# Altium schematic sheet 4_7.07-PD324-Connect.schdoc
size 848 x 601 mm; Symbol: Drawing-Symbol_A1; Device: Drawing-Symbol_A1; Company: 嘉立创EDA; Version: V1.0; Page Size: A1; @Project Name: PD324; @Page Count: 4; @Update Date: 2025-05-07; @Create Date: 2025-05-06; @Schematic Name: Schematic1; @Page No: 4; @Page Name: 7.07-PD324-Connect; @Create Time: 08:53:41; @Update Time: 09:37:43; Width: 3304; Height: 2338; Region Start: 1; X Region Count: 6; Y Region Count: 4; Blade Width: 10; Title Block Position: 3; @Board Name: Board1
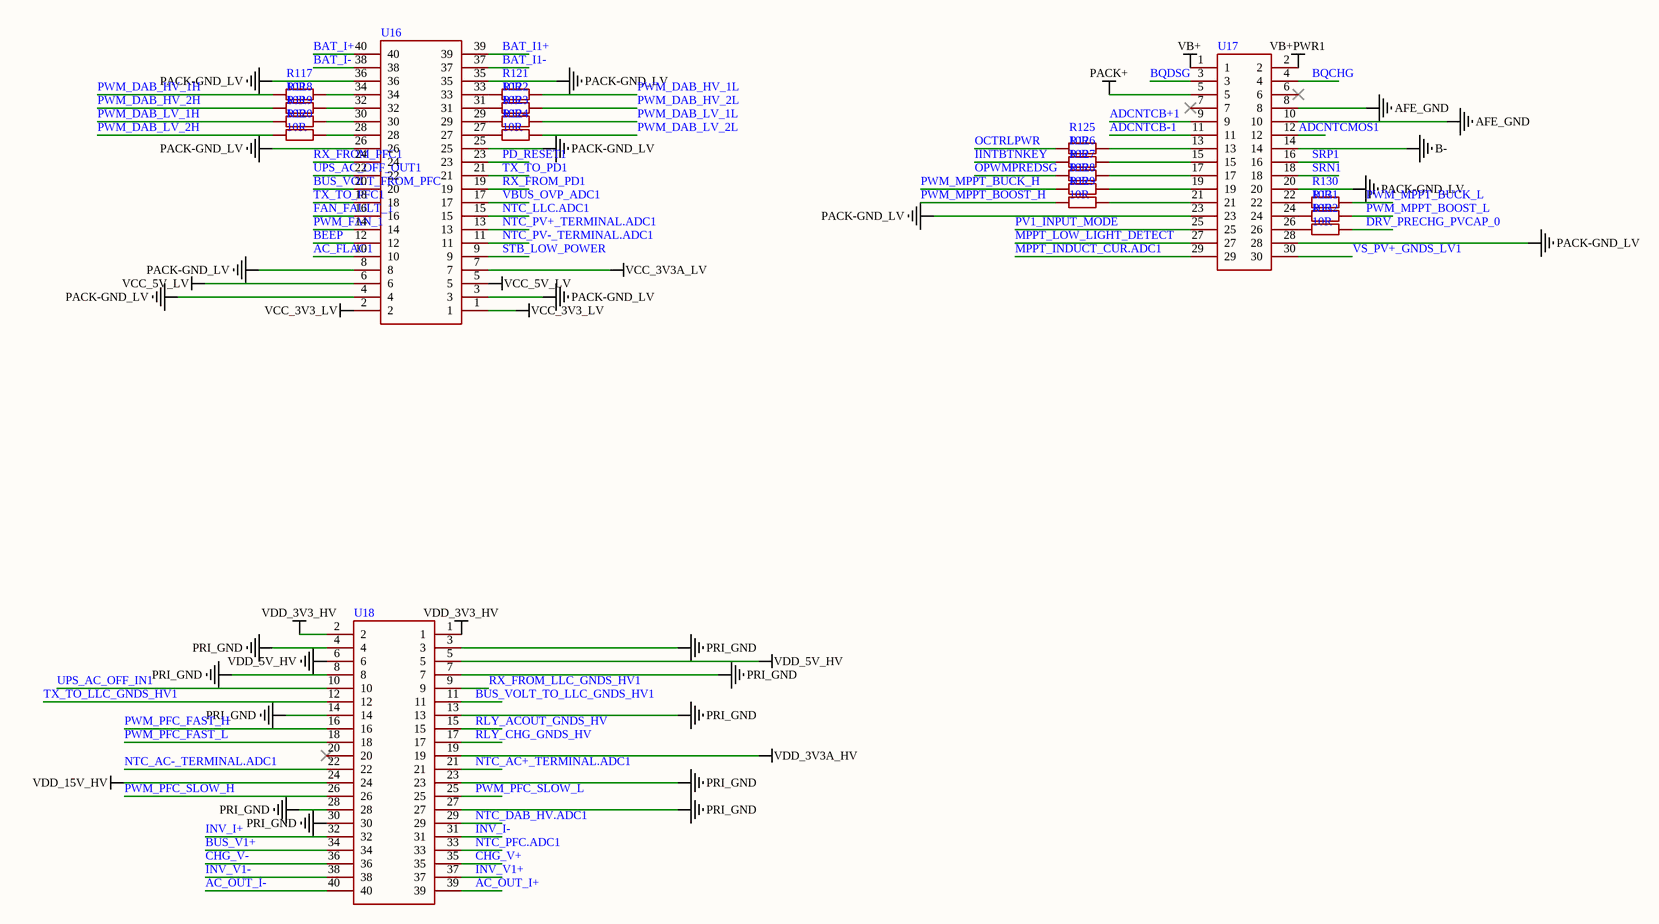
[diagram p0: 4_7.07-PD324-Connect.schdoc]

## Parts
R117  10R  [R0603]
R118  10R  [R0603]
R119  10R  [R0603]
R120  10R  [R0603]
R121  10R  [R0603]
R122  10R  [R0603]
R123  10R  [R0603]
R124  10R  [R0603]
R125  10R  [R0603]
R126  10R  [R0603]
R127  10R  [R0603]
R128  10R  [R0603]
R129  10R  [R0603]
R130  10R  [R0603]
R131  10R  [R0603]
R132  10R  [R0603]
U16  (no value)
U17  (no value)
U18  (no value)

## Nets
AFE_GND: U17.8 U17.10
B-: U17.14
PACK+: U17.5
PACK-GND_LV: U16.3 U16.4 U16.8 U16.25 U16.26 U16.35 U16.36 U17.20 U17.23 U17.28
PRI_GND: U18.3 U18.4 U18.7 U18.8 U18.13 U18.14 U18.23 U18.27 U18.28 U18.30
VB+: U17.1
VB+PWR1: U17.2
VCC_3V3_LV: U16.1 U16.2
VCC_3V3A_LV: U16.7
VCC_5V_LV: U16.5 U16.6
VDD_3V3_HV: U18.1 U18.2
VDD_3V3A_HV: U18.19
VDD_5V_HV: U18.5 U18.6
VDD_15V_HV: U18.24
AC_FLAG1: U16.10
AC_OUT_I+: U18.39
AC_OUT_I-: U18.40
ADCNTCB+1: U17.9
ADCNTCB-1: U17.11
ADCNTCMOS1: U17.12
BAT_I1+: U16.39
BAT_I1-: U16.37
BAT_I+: U16.40
BAT_I-: U16.38
BEEP: U16.12
BQCHG: U17.4
BQDSG: U17.3
BUS_V1+: U18.34
BUS_VOLT_FROM_PFC: U16.20
BUS_VOLT_TO_LLC_GNDS_HV1: U18.11
CHG_V+: U18.35
CHG_V-: U18.36
DRV_PRECHG_PVCAP_0: R132.2
FAN_FAULT_1: U16.16
IINTBTNKEY: R126.1
INV_I+: U18.32
INV_I-: U18.31
INV_V1+: U18.37
INV_V1-: U18.38
MPPT_INDUCT_CUR.ADC1: U17.29
MPPT_LOW_LIGHT_DETECT: U17.27
NTC_AC+_TERMINAL.ADC1: U18.21
NTC_AC-_TERMINAL.ADC1: U18.22
NTC_DAB_HV.ADC1: U18.29
NTC_LLC.ADC1: U16.15
NTC_PFC.ADC1: U18.33
NTC_PV+_TERMINAL.ADC1: U16.13
NTC_PV-_TERMINAL.ADC1: U16.11
OCTRLPWR: R125.1
OPWMPREDSG: R127.1
PD_RESET1: U16.23
PV1_INPUT_MODE: U17.25
PWM_DAB_HV_1H: R117.1
PWM_DAB_HV_1L: R121.2
PWM_DAB_HV_2H: R118.1
PWM_DAB_HV_2L: R122.2
PWM_DAB_LV_1H: R119.1
PWM_DAB_LV_1L: R123.2
PWM_DAB_LV_2H: R120.1
PWM_DAB_LV_2L: R124.2
PWM_FAN_1: U16.14
PWM_MPPT_BOOST_H: R129.1
PWM_MPPT_BOOST_L: R131.2
PWM_MPPT_BUCK_H: R128.1
PWM_MPPT_BUCK_L: R130.2
PWM_PFC_FAST_H: U18.16
PWM_PFC_FAST_L: U18.18
PWM_PFC_SLOW_H: U18.26
PWM_PFC_SLOW_L: U18.25
RLY_ACOUT_GNDS_HV: U18.15
RLY_CHG_GNDS_HV: U18.17
RX_FROM_LLC_GNDS_HV1: U18.9
RX_FROM_PD1: U16.19
RX_FROM_PFC1: U16.24
SRN1: U17.18
SRP1: U17.16
STB_LOW_POWER: U16.9
TX_TO_LLC_GNDS_HV1: U18.12
TX_TO_PD1: U16.21
TX_TO_PFC1: U16.18
UPS_AC_OFF_IN1: U18.10
UPS_AC_OFF_OUT1: U16.22
VBUS_OVP_ADC1: U16.17
VS_PV+_GNDS_LV1: U17.30
NetR117_2: R117.2 U16.34
NetR118_2: R118.2 U16.32
NetR119_2: R119.2 U16.30
NetR120_2: R120.2 U16.28
NetR121_1: R121.1 U16.33
NetR122_1: R122.1 U16.31
NetR123_1: R123.1 U16.29
NetR124_1: R124.1 U16.27
NetR125_2: R125.2 U17.13
NetR126_2: R126.2 U17.15
NetR127_2: R127.2 U17.17
NetR128_2: R128.2 U17.19
NetR129_2: R129.2 U17.21
NetR130_1: R130.1 U17.22
NetR131_1: R131.1 U17.24
NetR132_1: R132.1 U17.26

Not connected (* = marked no-connect by the designer): U17 6* 7*; U18 20*

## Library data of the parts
R117-R132 = Res_0603: Symbol: 电阻; Convert to PCB: yes
U16 U18 = Connector2*20: Add into BOM: yes
U17 = connector2*15: Add into BOM: yes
